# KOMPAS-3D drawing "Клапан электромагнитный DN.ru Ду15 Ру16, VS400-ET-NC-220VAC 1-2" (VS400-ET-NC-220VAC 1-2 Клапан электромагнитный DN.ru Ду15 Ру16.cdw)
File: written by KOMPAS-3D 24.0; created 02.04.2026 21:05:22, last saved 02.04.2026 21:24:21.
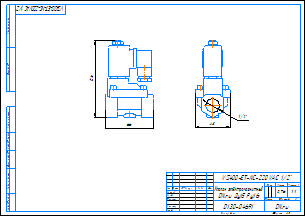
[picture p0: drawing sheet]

Document properties: c3d_UniqueCompID: ef56311e-7521-43dc-8291-0e6108b3d81d; Обозначение: VS400-ET-NC-220VAC 1-2; Наименование: Клапан электромагнитный DN.ru Ду15 Ру16; Автор: artio; Класс точности: c; Знак неуказанной шероховатости: Шероховатость не задана; Рассекать на разрезах: Да; c3d_UniqueCompID: ef56311e-7521-43dc-8291-0e6108b3d81d; Обозначение: VS400-ET-NC-220VAC 3-8; Наименование: Клапан электромагнитный DN.ru Ду10 Ру16; Автор: artio; Класс точности: c; Знак неуказанной шероховатости: Шероховатость не задана; Рассекать на разрезах: Да; Автор: artio; Форматы листов документа: A3; Полное имя файла: VS400-ET-NC-220VAC 1-2 Клапан электромагнитный DN.ru Ду15 Ру16.m3d; Масса: 0.759; Наименование: Клапан электромагнитный DN.ru Ду15 Ру16; Количество листов документа: 1; Примечание: D130-04691

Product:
- Body: Тело 1  | qty 1
    Масса: 1.030062
- Part/product: Клапан электромагнитный DN.ru Ду15 Ру16  | designation VS400-ET-NC-220VAC 1-2
    Масса: 0.759
    Раздел спецификации: Прочие изделия
    Примечание: D130-04691
    additional columns: ef56311e-7521-43dc-8291-0e6108b3d81d; VS400-ET-NC-220VAC 1-2; artio; c; Шероховатость не задана; Да

Views: Вид 1, Спереди, Проекционный вид 2
Referenced files in C:\Users\artio\OneDrive\Рабочий стол\Клапан электромагнитный DN.ru VS4x-xT-NC-x\DN10\: VS400-ET-NC-220VAC 3-8 Клапан электромагнитный DN.ru Ду10 Ру16.m3d, VS400-ET-NC-220VAC 3-8 Клапан электромагнитный DN.ru Ду10 Ру16.cdw
Referenced files in C:\Users\artio\OneDrive\Рабочий стол\Клапан электромагнитный DN.ru VS4x-xT-NC-x\DN15\: VS400-ET-NC-220VAC 1-2 Клапан электромагнитный DN.ru Ду15 Ру16.m3d
Referenced files in C:\Users\artio\OneDrive\Рабочий стол\Клапан электромагнитный DN.ru\VS400\VS400-ET-NC\VS400-ET-NC-220VAC\Ду15\: VS400-ET-NC-220VAC 1-2 Клапан электромагнитный DN.ru Ду15 Ру16.m3d
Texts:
  VS400-ET-NC-220VAC 1-2
  Линейный размер
  Клапан электромагнитный
  DN.ru Ду15 Ру16
  VS400-ET-NC-220VAC 1/2"
  VS400-ET-NC-220VAC 1/2"-
  Клапан электромагнитный DN.ru Ду15 Ру16
  VS400-ET-NC-220VAC 1-2 Клапан электромагнитный DN.ru Ду15 Ру16
Dimensions and other numbers on the sheet: 0; 3; 2; 4; 48; 1/2"; 66; 106; 1:1; 1; 0,76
